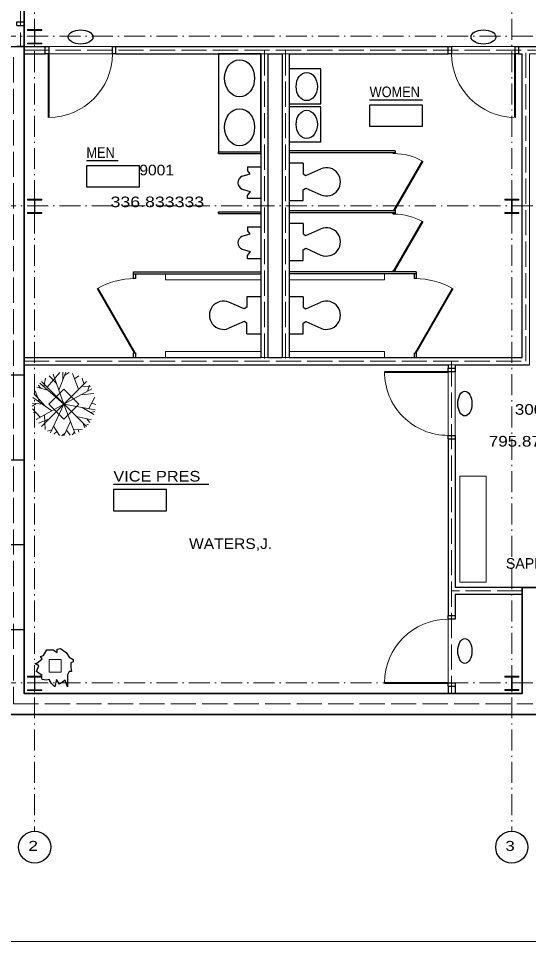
# Model space of a CAD drawing. Extents: x -118748 to -117136, y -118748 to -117596.
# Drawn here: x -118499.3 to -118268.3, y -118748.4 to -118330.4 of the extents above; entities that cross this region are included whole.
import ezdxf
from ezdxf.enums import TextEntityAlignment as Align

# ---------------------------------------------------------------- set-up
doc = ezdxf.new("R2010")
doc.units = 0
doc.header["$LTSCALE"] = 1.9
doc.header["$PDMODE"] = 32
doc.header["$PDSIZE"] = 0.95
doc.linetypes.add('DOT_DASHED', pattern=[7.7, 5, -1.2, 0.3, -1.2])
doc.linetypes.add('LONG_DASHED', pattern=[7.5, 6, -1.5])
for name, color, linetype, lineweight in [('10', 7, 'DOT_DASHED', 13), ('11', 7, 'Continuous', 25), ('12', 7, 'Continuous', 13), ('15', 7, 'Continuous', 13), ('16', 7, 'Continuous', 13), ('17', 7, 'Continuous', 25), ('2', 7, 'Continuous', 35), ('23', 7, 'Continuous', 25), ('25', 7, 'Continuous', 13), ('26', 7, 'Continuous', 25), ('3', 7, 'Continuous', 35), ('30', 7, 'Continuous', 13), ('31', 7, 'Continuous', 25), ('4', 7, 'Continuous', 35), ('42', 7, 'Continuous', 25), ('45', 7, 'Continuous', 25), ('5', 7, 'Continuous', 13), ('6', 7, 'Continuous', 13), ('60', 7, 'LONG_DASHED', 13)]:
    doc.layers.add(name, color=color, linetype=linetype, lineweight=lineweight)
doc.layers.add('53', color=7, linetype='Continuous')

msp = doc.modelspace()

# ---------------------------------------------------------------- linework, layer by layer
at = {"layer": '10'}
for p, q in [((-118491.921, -117628.339), (-118491.921, -118698.41)), ((-118275.921, -117628.339), (-118275.921, -118698.41)), ((-118641.571, -118338.41), (-117285.521, -118338.41)), ((-118641.571, -118415.21), (-117285.521, -118415.21)), ((-118641.571, -118631.21), (-117285.521, -118631.21))]:
    msp.add_line(p, q, dxfattribs=at)
at = {"layer": '11'}
for centre in [(-118491.921, -118705.61), (-118275.921, -118705.61)]:
    msp.add_circle(centre, 7.253, dxfattribs=at)
at = {"layer": '12'}
for points in [[(-118495.104, -118341.962), (-118488.688, -118341.962), (-118488.688, -118341.566), (-118491.772, -118341.566), (-118491.772, -118335.862), (-118488.688, -118335.862), (-118488.688, -118335.466), (-118495.104, -118335.466), (-118495.104, -118335.862), (-118492.02, -118335.862), (-118492.02, -118341.566), (-118495.104, -118341.566)], [(-118495.104, -118418.762), (-118488.688, -118418.762), (-118488.688, -118418.366), (-118491.772, -118418.366), (-118491.772, -118412.662), (-118488.688, -118412.662), (-118488.688, -118412.266), (-118495.104, -118412.266), (-118495.104, -118412.662), (-118492.02, -118412.662), (-118492.02, -118418.366), (-118495.104, -118418.366)], [(-118279.104, -118418.762), (-118272.688, -118418.762), (-118272.688, -118418.366), (-118275.772, -118418.366), (-118275.772, -118412.662), (-118272.688, -118412.662), (-118272.688, -118412.266), (-118279.104, -118412.266), (-118279.104, -118412.662), (-118276.02, -118412.662), (-118276.02, -118418.366), (-118279.104, -118418.366)], [(-118495.104, -118634.762), (-118488.688, -118634.762), (-118488.688, -118634.366), (-118491.772, -118634.366), (-118491.772, -118628.662), (-118488.688, -118628.662), (-118488.688, -118628.266), (-118495.104, -118628.266), (-118495.104, -118628.662), (-118492.02, -118628.662), (-118492.02, -118634.366), (-118495.104, -118634.366)], [(-118279.098, -118634.72), (-118272.682, -118634.72), (-118272.682, -118634.324), (-118275.766, -118634.324), (-118275.766, -118628.62), (-118272.682, -118628.62), (-118272.682, -118628.224), (-118279.098, -118628.224), (-118279.098, -118628.62), (-118276.014, -118628.62), (-118276.014, -118634.324), (-118279.098, -118634.324)]]:
    msp.add_lwpolyline(points, close=True, dxfattribs=at)
at = {"layer": '15', "lineweight": 25}
for p, q in [((-118586.321, -118343.21), (-118496.721, -118343.21)), ((-118496.721, -118343.21), (-118496.721, -118492.01)), ((-118496.721, -118492.01), (-118506.321, -118492.01)), ((-118496.721, -118530.41), (-118506.321, -118530.41)), ((-118496.721, -118530.41), (-118496.721, -118568.81)), ((-118496.721, -118568.81), (-118506.321, -118568.81)), ((-118271.121, -118588.01), (-118261.521, -118588.01)), ((-118271.121, -118636.01), (-118271.121, -118588.01)), ((-118496.721, -118607.21), (-118506.321, -118607.21)), ((-118496.721, -118607.21), (-118496.721, -118636.01)), ((-118496.721, -118636.01), (-118271.121, -118636.01)), ((-118506.321, -118645.61), (-118261.521, -118645.61))]:
    msp.add_line(p, q, dxfattribs=at)
at = {"layer": '15'}
msp.add_lwpolyline([(-118287.438, -118585.726), (-118299.438, -118585.726), (-118299.438, -118537.726), (-118287.438, -118537.726)], close=True, dxfattribs=at)
at = {"layer": '16'}
for p, q in [((-118496.721, -118492.01), (-118496.721, -118530.41)), ((-118496.721, -118568.81), (-118496.721, -118607.21))]:
    msp.add_line(p, q, dxfattribs=at)
at = {"layer": '17'}
for p, q in [((-118340.261, -118367.269), (-118316.261, -118367.269)), ((-118468.49, -118394.746), (-118454.09, -118394.746)), ((-118456.277, -118541.293), (-118413.077, -118541.293))]:
    msp.add_line(p, q, dxfattribs=at)
msp.add_lwpolyline([(-118488.577, -118627.929), (-118491.111, -118626.119), (-118490.025, -118623.584), (-118491.836, -118622.498), (-118491.111, -118622.498), (-118488.577, -118620.326), (-118489.301, -118619.24), (-118487.853, -118618.878), (-118486.405, -118616.344), (-118483.509, -118616.344), (-118481.698, -118617.43), (-118481.698, -118615.982), (-118480.25, -118615.62), (-118477.716, -118617.43), (-118476.268, -118619.602), (-118474.458, -118620.688), (-118474.458, -118621.774), (-118475.544, -118622.136), (-118475.544, -118624.308), (-118475.182, -118626.119), (-118476.268, -118626.119), (-118476.992, -118627.567), (-118476.992, -118632.997), (-118478.078, -118630.101), (-118479.164, -118630.825), (-118480.612, -118631.911), (-118482.061, -118629.739), (-118482.785, -118632.997), (-118484.233, -118631.549), (-118485.319, -118629.739), (-118486.767, -118630.101), (-118488.577, -118629.739), (-118488.939, -118627.929)], dxfattribs=at)
at = {"layer": '17', "lineweight": 13}
msp.add_lwpolyline([(-118485.319, -118626.481), (-118485.319, -118620.688), (-118479.888, -118620.688), (-118479.888, -118626.481)], close=True, dxfattribs=at)
at = {"layer": '2', "lineweight": 13}
msp.add_lwpolyline([(-118748.365, -118748.365), (-117365.965, -118748.365), (-117365.965, -117826.765), (-118748.365, -117826.765), (-118748.365, -118748.365), (-117135.565, -118748.365), (-117135.565, -117596.365), (-118748.365, -117596.365)], close=True, dxfattribs=at)
at = {"layer": '23'}
for p, q in [((-118499.921, -118333.61), (-118496.721, -118333.61)), ((-118496.721, -118333.61), (-118496.721, -118343.21)), ((-118496.721, -118343.21), (-118499.921, -118343.21)), ((-118496.721, -118343.21), (-118496.721, -118346.41)), ((-118496.721, -118343.21), (-118487.121, -118343.21)), ((-118496.721, -118346.41), (-118487.121, -118346.41)), ((-118487.121, -118346.41), (-118487.121, -118343.21)), ((-118455.121, -118346.41), (-118455.121, -118343.21)), ((-118455.121, -118343.21), (-118304.721, -118343.21)), ((-118455.121, -118346.41), (-118389.521, -118346.41)), ((-118389.521, -118346.41), (-118389.521, -118484.01)), ((-118386.321, -118346.41), (-118379.921, -118346.41)), ((-118386.321, -118346.41), (-118386.321, -118484.01)), ((-118379.921, -118346.41), (-118379.921, -118484.01)), ((-118376.721, -118346.41), (-118376.721, -118484.01)), ((-118376.721, -118346.41), (-118304.721, -118346.41)), ((-118304.721, -118346.41), (-118304.721, -118343.21)), ((-118272.721, -118346.41), (-118272.721, -118343.21)), ((-118272.721, -118343.21), (-118123.175, -118343.21)), ((-118272.721, -118346.41), (-118271.121, -118346.41)), ((-118271.121, -118484.01), (-118271.121, -118346.41)), ((-118496.721, -118484.01), (-118496.721, -118487.21)), ((-118496.721, -118484.01), (-118389.521, -118484.01)), ((-118386.321, -118484.01), (-118379.921, -118484.01)), ((-118376.721, -118484.01), (-118271.121, -118484.01)), ((-118496.721, -118487.21), (-118304.721, -118487.21)), ((-118304.721, -118487.21), (-118304.721, -118488.81)), ((-118304.721, -118488.81), (-118301.521, -118488.81)), ((-118301.521, -118487.21), (-118267.921, -118487.21)), ((-118301.521, -118487.21), (-118301.521, -118488.81)), ((-118304.721, -118520.81), (-118301.521, -118520.81)), ((-118304.721, -118520.81), (-118304.721, -118600.81)), ((-118301.521, -118520.81), (-118301.521, -118588.01)), ((-118271.121, -118588.01), (-118301.521, -118588.01)), ((-118271.121, -118591.21), (-118271.121, -118588.01)), ((-118271.121, -118591.21), (-118301.521, -118591.21)), ((-118301.521, -118591.21), (-118301.521, -118600.81)), ((-118304.721, -118600.81), (-118301.521, -118600.81)), ((-118304.721, -118632.81), (-118301.521, -118632.81)), ((-118304.721, -118632.81), (-118304.721, -118636.01)), ((-118301.521, -118632.81), (-118301.521, -118636.01)), ((-118301.521, -118636.01), (-118304.721, -118636.01))]:
    msp.add_line(p, q, dxfattribs=at)
at = {"layer": '25', "lineweight": 40}
for p, q in [((-118485.521, -118375.21), (-118485.521, -118346.41)), ((-118274.321, -118375.21), (-118274.321, -118346.41)), ((-118333.521, -118490.41), (-118304.721, -118490.41)), ((-118333.521, -118631.21), (-118304.721, -118631.21))]:
    msp.add_line(p, q, dxfattribs=at)
at = {"layer": '25'}
for centre, start, end in [((-118485.521, -118346.41), 269.99998, 359.99998), ((-118274.321, -118346.41), 180.00001, 270), ((-118304.721, -118490.41), 179.99998, 269.99998), ((-118304.721, -118631.21), 90.00001, 180)]:
    msp.add_arc(centre, 28.8, start, end, dxfattribs=at)
at = {"layer": '26'}
for points in [[(-118499.921, -118333.61), (-118499.921, -118332.01), (-118496.721, -118332.01), (-118496.721, -118333.61)], [(-118487.121, -118343.21), (-118485.521, -118343.21), (-118485.521, -118346.41), (-118487.121, -118346.41)], [(-118455.121, -118346.41), (-118456.721, -118346.41), (-118456.721, -118343.21), (-118455.121, -118343.21)], [(-118304.721, -118343.21), (-118303.121, -118343.21), (-118303.121, -118346.41), (-118304.721, -118346.41)], [(-118272.721, -118346.41), (-118274.321, -118346.41), (-118274.321, -118343.21), (-118272.721, -118343.21)], [(-118301.521, -118488.81), (-118301.521, -118490.41), (-118304.721, -118490.41), (-118304.721, -118488.81)], [(-118304.721, -118520.81), (-118304.721, -118519.21), (-118301.521, -118519.21), (-118301.521, -118520.81)], [(-118301.521, -118600.81), (-118301.521, -118602.41), (-118304.721, -118602.41), (-118304.721, -118600.81)], [(-118304.721, -118632.81), (-118304.721, -118631.21), (-118301.521, -118631.21), (-118301.521, -118632.81)]]:
    msp.add_lwpolyline(points, dxfattribs=at)
at = {"layer": '3'}
msp.add_lwpolyline([(-117890.316, -118553.433), (-118075.926, -118553.433), (-118077.534, -118553.433), (-118077.559, -118555.032), (-118079.538, -118565.426), (-118080.102, -118566.923), (-118085.022, -118576.169), (-118086.007, -118577.43), (-118093.457, -118584.791), (-118094.773, -118585.701), (-118104.079, -118590.508), (-118105.606, -118590.985), (-118115.921, -118592.801), (-118119.121, -118592.81), (-118261.521, -118592.81), (-118261.521, -118645.61), (-118506.321, -118645.61), (-118506.321, -118352.81), (-118595.921, -118352.81)], dxfattribs=at)
at = {"layer": '30', "lineweight": 25}
for p, q in [((-118362.287, -118369.247), (-118376.687, -118369.247)), ((-118362.287, -118386.407), (-118376.687, -118386.407)), ((-118370.321, -118396.009), (-118376.721, -118396.009)), ((-118370.321, -118396.009), (-118370.321, -118400.785)), ((-118397.994, -118401.861), (-118394.321, -118400.81)), ((-118395.521, -118397.61), (-118395.521, -118399.21)), ((-118395.521, -118397.61), (-118389.521, -118397.61)), ((-118394.321, -118400.81), (-118395.521, -118399.21)), ((-118370.321, -118400.785), (-118369.2, -118401.518)), ((-118369.2, -118401.518), (-118362.277, -118398.482)), ((-118370.321, -118408.034), (-118369.2, -118407.301)), ((-118370.321, -118412.809), (-118370.321, -118408.034)), ((-118369.2, -118407.301), (-118362.277, -118410.337)), ((-118395.521, -118412.01), (-118395.521, -118410.41)), ((-118389.521, -118412.01), (-118395.521, -118412.01)), ((-118376.721, -118412.809), (-118370.321, -118412.809)), ((-118395.521, -118424.81), (-118395.521, -118426.41)), ((-118395.521, -118424.81), (-118389.521, -118424.81)), ((-118370.321, -118423.209), (-118376.721, -118423.209)), ((-118370.321, -118423.209), (-118370.321, -118427.985)), ((-118369.2, -118428.718), (-118362.277, -118425.682)), ((-118397.994, -118429.061), (-118394.321, -118428.01)), ((-118394.321, -118428.01), (-118395.521, -118426.41)), ((-118370.321, -118427.985), (-118369.2, -118428.718)), ((-118370.321, -118435.234), (-118369.2, -118434.501)), ((-118369.2, -118434.501), (-118362.277, -118437.537)), ((-118395.521, -118439.21), (-118395.521, -118437.61)), ((-118370.321, -118440.009), (-118370.321, -118435.234)), ((-118389.521, -118439.21), (-118395.521, -118439.21)), ((-118376.721, -118440.009), (-118370.321, -118440.009)), ((-118397.042, -118461.918), (-118403.965, -118458.882)), ((-118389.521, -118456.41), (-118395.921, -118456.41)), ((-118395.921, -118456.41), (-118395.921, -118461.185)), ((-118370.321, -118456.41), (-118376.721, -118456.41)), ((-118370.321, -118456.41), (-118370.321, -118461.185)), ((-118369.2, -118461.918), (-118362.277, -118458.882)), ((-118395.921, -118461.185), (-118397.042, -118461.918)), ((-118370.321, -118461.185), (-118369.2, -118461.918)), ((-118397.042, -118467.701), (-118403.965, -118470.737)), ((-118395.921, -118468.434), (-118397.042, -118467.701)), ((-118370.321, -118468.434), (-118369.2, -118467.701)), ((-118369.2, -118467.701), (-118362.277, -118470.737)), ((-118395.921, -118473.21), (-118395.921, -118468.434)), ((-118370.321, -118473.21), (-118370.321, -118468.434)), ((-118395.921, -118473.21), (-118389.521, -118473.21)), ((-118376.721, -118473.21), (-118370.321, -118473.21))]:
    msp.add_line(p, q, dxfattribs=at)
at = {"layer": '30'}
for p, q in [((-118486.252, -118497.428), (-118480.514, -118490.728)), ((-118481.987, -118495.682), (-118485.397, -118492.277)), ((-118478.671, -118505.009), (-118483.495, -118491.442)), ((-118480.919, -118498.686), (-118477.816, -118490.635)), ((-118479.135, -118494.057), (-118479.225, -118490.62)), ((-118478.294, -118491.876), (-118476.291, -118490.807)), ((-118472.002, -118498.341), (-118474.838, -118491.129)), ((-118473.838, -118493.673), (-118471.968, -118492.264)), ((-118489.09, -118497.88), (-118490.262, -118496.465)), ((-118478.671, -118505.009), (-118489.514, -118495.534)), ((-118468.489, -118515.192), (-118488.853, -118494.827)), ((-118488.853, -118515.192), (-118468.489, -118494.827)), ((-118487.738, -118497.087), (-118486.963, -118493.237)), ((-118470.608, -118496.946), (-118466.642, -118497.093)), ((-118469.594, -118495.932), (-118470.36, -118493.25)), ((-118468.027, -118499.227), (-118467.022, -118496.544)), ((-118487.046, -118506.067), (-118492.264, -118500.258)), ((-118489.741, -118504.159), (-118491.739, -118498.96)), ((-118485.906, -118498.687), (-118490.908, -118497.419)), ((-118478.671, -118505.009), (-118466.018, -118498.135)), ((-118470.945, -118500.812), (-118465.073, -118500.272)), ((-118488.558, -118504.997), (-118493.067, -118504.671)), ((-118491.104, -118504.813), (-118493.037, -118506.001)), ((-118484.177, -118508.098), (-118492.758, -118502.023)), ((-118478.671, -118505.009), (-118491.23, -118512.055)), ((-118478.671, -118505.009), (-118484.796, -118518.042)), ((-118478.671, -118505.009), (-118473.556, -118518.471)), ((-118478.671, -118505.009), (-118464.507, -118507.605)), ((-118467.346, -118507.085), (-118464.614, -118501.883)), ((-118466.037, -118504.593), (-118464.272, -118505.185)), ((-118489.368, -118511.01), (-118492.9, -118507.218)), ((-118491.138, -118509.11), (-118492.588, -118508.709)), ((-118470.38, -118506.529), (-118465.078, -118509.763)), ((-118466.618, -118508.823), (-118464.679, -118508.413)), ((-118485.517, -118511.855), (-118490.17, -118513.678)), ((-118487.404, -118509.909), (-118487.224, -118516.594)), ((-118475.658, -118512.94), (-118478.772, -118519.409)), ((-118472.966, -118510.714), (-118466.167, -118512.151)), ((-118470.177, -118513.503), (-118469.172, -118515.832)), ((-118468.351, -118511.69), (-118466.936, -118513.355)), ((-118484.128, -118516.621), (-118486.109, -118517.339)), ((-118483.396, -118515.062), (-118480.65, -118519.273)), ((-118481.811, -118517.493), (-118483.225, -118518.67)), ((-118477.544, -118516.859), (-118475.866, -118519.134)), ((-118473.859, -118517.674), (-118474.873, -118518.9)), ((-118474.369, -118516.332), (-118470.23, -118516.676)), ((-118472.156, -118516.516), (-118471.865, -118517.699)), ((-118468.96, -118514.721), (-118467.474, -118514.064)), ((-118478.207, -118518.235), (-118479.609, -118519.379))]:
    msp.add_line(p, q, dxfattribs=at)
at = {"layer": '30', "lineweight": 25}
msp.add_lwpolyline([(-118389.521, -118346.41), (-118408.721, -118346.41), (-118408.721, -118390.81), (-118389.521, -118390.81)], close=True, dxfattribs=at)
for points in [[(-118362.287, -118369.247), (-118362.287, -118353.247), (-118376.687, -118353.247)], [(-118362.287, -118386.407), (-118362.287, -118370.406), (-118376.687, -118370.406)], [(-118397.994, -118407.758), (-118394.321, -118408.81), (-118395.521, -118410.41)], [(-118397.994, -118434.958), (-118394.321, -118436.01), (-118395.521, -118437.61)]]:
    msp.add_lwpolyline(points, dxfattribs=at)
at = {"layer": '30'}
msp.add_lwpolyline([(-118478.668, -118511.862), (-118485.456, -118505.074), (-118478.668, -118498.286), (-118471.879, -118505.074)], close=True, dxfattribs=at)
at = {"layer": '30', "lineweight": 25}
for centre, radius, start, end in [((-118359.844, -118404.409), 6.407, 247.68829, 112.31269), ((-118396.701, -118404.81), 3.22, 113.68782, 246.31411), ((-118359.844, -118431.609), 6.407, 247.68829, 112.31269), ((-118396.701, -118432.01), 3.22, 113.68782, 246.31411), ((-118406.397, -118464.81), 6.407, 67.68829, 292.31269), ((-118359.844, -118464.809), 6.407, 247.68829, 112.31269)]:
    msp.add_arc(centre, radius, start, end, dxfattribs=at)
for centre, major_axis, ratio in [((-118399.121, -118357.51), (0, 8.4), 0.809536), ((-118368.721, -118361.258), (0, -6.4), 0.75), ((-118399.121, -118379.71), (0, 8.4), 0.809536), ((-118368.721, -118378.418), (0, -6.4), 0.75)]:
    msp.add_ellipse(centre, major_axis=major_axis, ratio=ratio, dxfattribs=at)
at = {"layer": '30'}
msp.add_point((-118478.671, -118505.009), dxfattribs=at)
at = {"layer": '31'}
for p, q in [((-118408.721, -118390.81), (-118389.521, -118390.81)), ((-118408.721, -118391.61), (-118408.721, -118390.81)), ((-118408.721, -118391.61), (-118389.521, -118391.61)), ((-118328.721, -118390.409), (-118376.721, -118390.409)), ((-118328.721, -118391.209), (-118376.721, -118391.209)), ((-118328.721, -118390.409), (-118328.721, -118391.209)), ((-118328.721, -118417.609), (-118376.721, -118417.609)), ((-118328.721, -118417.609), (-118328.721, -118418.409)), ((-118408.721, -118418.01), (-118389.521, -118418.01)), ((-118408.721, -118418.81), (-118408.721, -118418.01)), ((-118408.721, -118418.81), (-118389.521, -118418.81)), ((-118328.721, -118418.409), (-118376.721, -118418.409)), ((-118447.121, -118445.21), (-118389.521, -118445.21)), ((-118447.121, -118446.01), (-118447.121, -118445.21)), ((-118447.121, -118446.01), (-118389.52, -118446.01)), ((-118319.121, -118445.209), (-118376.721, -118445.209)), ((-118319.121, -118446.01), (-118376.721, -118446.01)), ((-118319.121, -118445.209), (-118319.121, -118446.01))]:
    msp.add_line(p, q, dxfattribs=at)
at = {"layer": '31', "lineweight": 40}
for p, q in [((-118316.321, -118395.04), (-118329.121, -118417.209)), ((-118316.321, -118422.44), (-118329.121, -118444.609)), ((-118463.521, -118452.711), (-118446.721, -118481.81)), ((-118302.737, -118452.711), (-118319.537, -118481.81))]:
    msp.add_line(p, q, dxfattribs=at)
at = {"layer": '31'}
for points in [[(-118328.721, -118391.209), (-118328.721, -118391.609), (-118329.521, -118391.609), (-118329.521, -118391.209)], [(-118329.521, -118417.609), (-118329.521, -118417.209), (-118328.721, -118417.209), (-118328.721, -118417.609)], [(-118328.721, -118418.409), (-118328.721, -118419.009), (-118329.521, -118419.009), (-118329.521, -118418.409)], [(-118446.321, -118446.01), (-118446.321, -118448.21), (-118447.121, -118448.21), (-118447.121, -118446.01)], [(-118329.521, -118445.209), (-118329.521, -118444.609), (-118328.721, -118444.609), (-118328.721, -118445.209)], [(-118319.137, -118446.009), (-118319.137, -118448.21), (-118319.937, -118448.21), (-118319.937, -118446.01)], [(-118447.121, -118484.01), (-118447.121, -118481.81), (-118446.321, -118481.81), (-118446.321, -118484.01)], [(-118319.937, -118484.01), (-118319.937, -118481.81), (-118319.137, -118481.81), (-118319.137, -118484.01)]]:
    msp.add_lwpolyline(points, dxfattribs=at)
at = {"layer": '31', "lineweight": 13}
for points in [[(-118389.521, -118448.81), (-118432.721, -118448.81), (-118432.721, -118446.01)], [(-118376.721, -118448.81), (-118333.521, -118448.81), (-118333.521, -118446.01)], [(-118389.521, -118481.209), (-118432.721, -118481.209), (-118432.721, -118484.01)], [(-118376.721, -118481.209), (-118333.521, -118481.209), (-118333.521, -118484.01)]]:
    msp.add_lwpolyline(points, dxfattribs=at)
for centre, radius, start, end in [((-118329.121, -118417.209), 25.599, 60.00001, 89.99999), ((-118329.121, -118444.609), 25.599, 60.00001, 89.99999), ((-118446.721, -118481.81), 33.6, 90.00001, 119.99999), ((-118319.537, -118481.81), 33.6, 60.00001, 89.99999)]:
    msp.add_arc(centre, radius, start, end, dxfattribs=at)
at = {"layer": '4'}
msp.add_lwpolyline([(-118496.721, -117964.01), (-118496.721, -118636.01), (-118271.121, -118636.01), (-118271.121, -118588.01), (-118115.969, -118588.01), (-118106.1, -118586.234), (-118096.66, -118581.314), (-118089.115, -118573.804), (-118084.156, -118564.399), (-118081.154, -118548.633), (-118079.134, -118548.633), (-117884.057, -118548.587), (-117881.646, -118565.336), (-117876.897, -118574.111), (-117869.271, -118581.538), (-117859.789, -118586.351), (-117850.271, -118588.01), (-117695.121, -118588.01), (-117695.121, -118636.01), (-117469.521, -118636.01), (-117469.521, -117964.01)], close=True, dxfattribs=at)
at = {"layer": '42'}
for centre, major_axis in [((-118471.121, -118338.81), (-5.6, 0)), ((-118288.721, -118338.81), (-5.6, 0)), ((-118297.121, -118504.81), (0, -5.6)), ((-118297.121, -118616.81), (0, -5.6))]:
    msp.add_ellipse(centre, major_axis=major_axis, ratio=0.571429, dxfattribs=at)
at = {"layer": '45'}
for points in [[(-118340.261, -118369.669), (-118340.261, -118379.269), (-118316.261, -118379.269), (-118316.261, -118369.669)], [(-118468.49, -118397.146), (-118468.49, -118406.746), (-118444.49, -118406.746), (-118444.49, -118397.146)], [(-118456.277, -118543.693), (-118456.277, -118553.293), (-118432.277, -118553.293), (-118432.277, -118543.693)]]:
    msp.add_lwpolyline(points, close=True, dxfattribs=at)
at = {"layer": '5'}
for points in [[(-118115.969, -118588.01), (-118271.121, -118588.01), (-118271.121, -118636.01), (-118496.721, -118636.01), (-118496.721, -117964.01)], [(-118123.174, -118415.21), (-118123.175, -118343.21), (-118272.721, -118343.21), (-118496.721, -118343.21), (-118496.721, -118333.61), (-118496.721, -118301.61), (-118496.721, -118295.21), (-118463.121, -118295.21), (-118123.171, -118295.21), (-118123.171, -118184.81)], [(-118082.334, -118477.77), (-118082.358, -118554.958), (-118084.029, -118563.732), (-118084.594, -118565.229), (-118088.804, -118573.214), (-118089.789, -118574.475), (-118096.188, -118580.843), (-118097.504, -118581.753), (-118105.509, -118585.926), (-118107.036, -118586.403), (-118115.921, -118588.001), (-118301.521, -118588.01), (-118301.521, -118520.81), (-118301.521, -118487.21), (-118267.921, -118487.21), (-118267.921, -118346.41)]]:
    msp.add_lwpolyline(points, dxfattribs=at)
msp.add_lwpolyline([(-118304.721, -118636.01), (-118304.721, -118632.81), (-118304.721, -118487.21), (-118496.721, -118487.21), (-118496.721, -118636.01)], close=True, dxfattribs=at)
at = {"layer": '6'}
for points in [[(-118496.721, -118343.21), (-118123.171, -118343.21), (-118123.171, -118295.21), (-118496.721, -118295.21)], [(-118496.721, -118346.41), (-118271.121, -118346.41), (-118271.121, -118484.01), (-118496.721, -118484.01)]]:
    msp.add_lwpolyline(points, close=True, dxfattribs=at)
for points in [[(-118496.721, -118636.01), (-118496.721, -118487.21), (-118301.521, -118487.21), (-118267.921, -118487.21), (-118267.921, -118346.41), (-118126.375, -118346.41), (-118126.374, -118415.21)], [(-118119.121, -118588.01), (-118271.121, -118588.01), (-118271.121, -118636.01), (-118496.721, -118636.01)]]:
    msp.add_lwpolyline(points, dxfattribs=at)
at = {"layer": '60'}
for p, q in [((-118498.321, -118180.01), (-118498.321, -118343.21)), ((-118496.721, -118344.81), (-118124.774, -118344.81)), ((-118387.921, -118344.81), (-118387.921, -118485.61)), ((-118378.321, -118344.81), (-118378.321, -118485.61)), ((-118303.121, -118485.61), (-118303.121, -118636.01)), ((-118271.121, -118589.61), (-118303.121, -118589.61))]:
    msp.add_line(p, q, dxfattribs=at)
for points in [[(-118496.721, -118485.61), (-118269.521, -118485.61), (-118269.521, -118344.81)], [(-118501.521, -118348.01), (-118501.521, -118640.81), (-118266.321, -118640.81)]]:
    msp.add_lwpolyline(points, dxfattribs=at)

# ---------------------------------------------------------------- texts
at = {"layer": '11'}
for s, width, p in [(' 2 ', 1.3, (-118492.601, -118707.31)), (' 3 ', 1.25, (-118276.654, -118707.31))]:
    msp.add_text(s, height=4.518, dxfattribs=dict(at, width=width)).set_placement(p, align=Align.CENTER)
at = {"layer": '17'}
for s, width, p in [('WOMEN', 0.9, (-118340.261, -118366.069)), ('MEN', 0.9, (-118468.49, -118393.546)), ('VICE PRES', 1.15, (-118456.277, -118540.093))]:
    msp.add_text(s, height=4.8, dxfattribs=dict(at, width=width)).set_placement(p)
at = {"layer": '45'}
for s, width, p in [('9001', 1.1, (-118436.682, -118401.477)), ('336.833333', 1.25, (-118436.361, -118415.877)), ('3000', 1.2, (-118265.928, -118509.857)), ('795.871394', 1.2, (-118265.928, -118524.257))]:
    msp.add_text(s, height=4.8, dxfattribs=dict(at, width=width)).set_placement(p, align=Align.CENTER)
at = {"layer": '53', "width": 1.1}
msp.add_text('WATERS,J.', height=4.8, dxfattribs=at).set_placement((-118422.027, -118570.616))
at = {"layer": '53'}
msp.add_text('SAPP,M.', height=4.8, dxfattribs=at).set_placement((-118278.564, -118579.582))

doc.saveas('drawing.dxf')
